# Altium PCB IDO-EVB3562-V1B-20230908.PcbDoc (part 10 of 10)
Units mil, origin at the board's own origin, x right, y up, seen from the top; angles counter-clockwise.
Board outline 5314.96 x 3543.31 mil, 4 copper layers (TOP, L2-VCC, L3-GND, BOTTOM), stack 28.8 mil thick; 747 components, 560 nets, 2514 pads, 1964 vias.
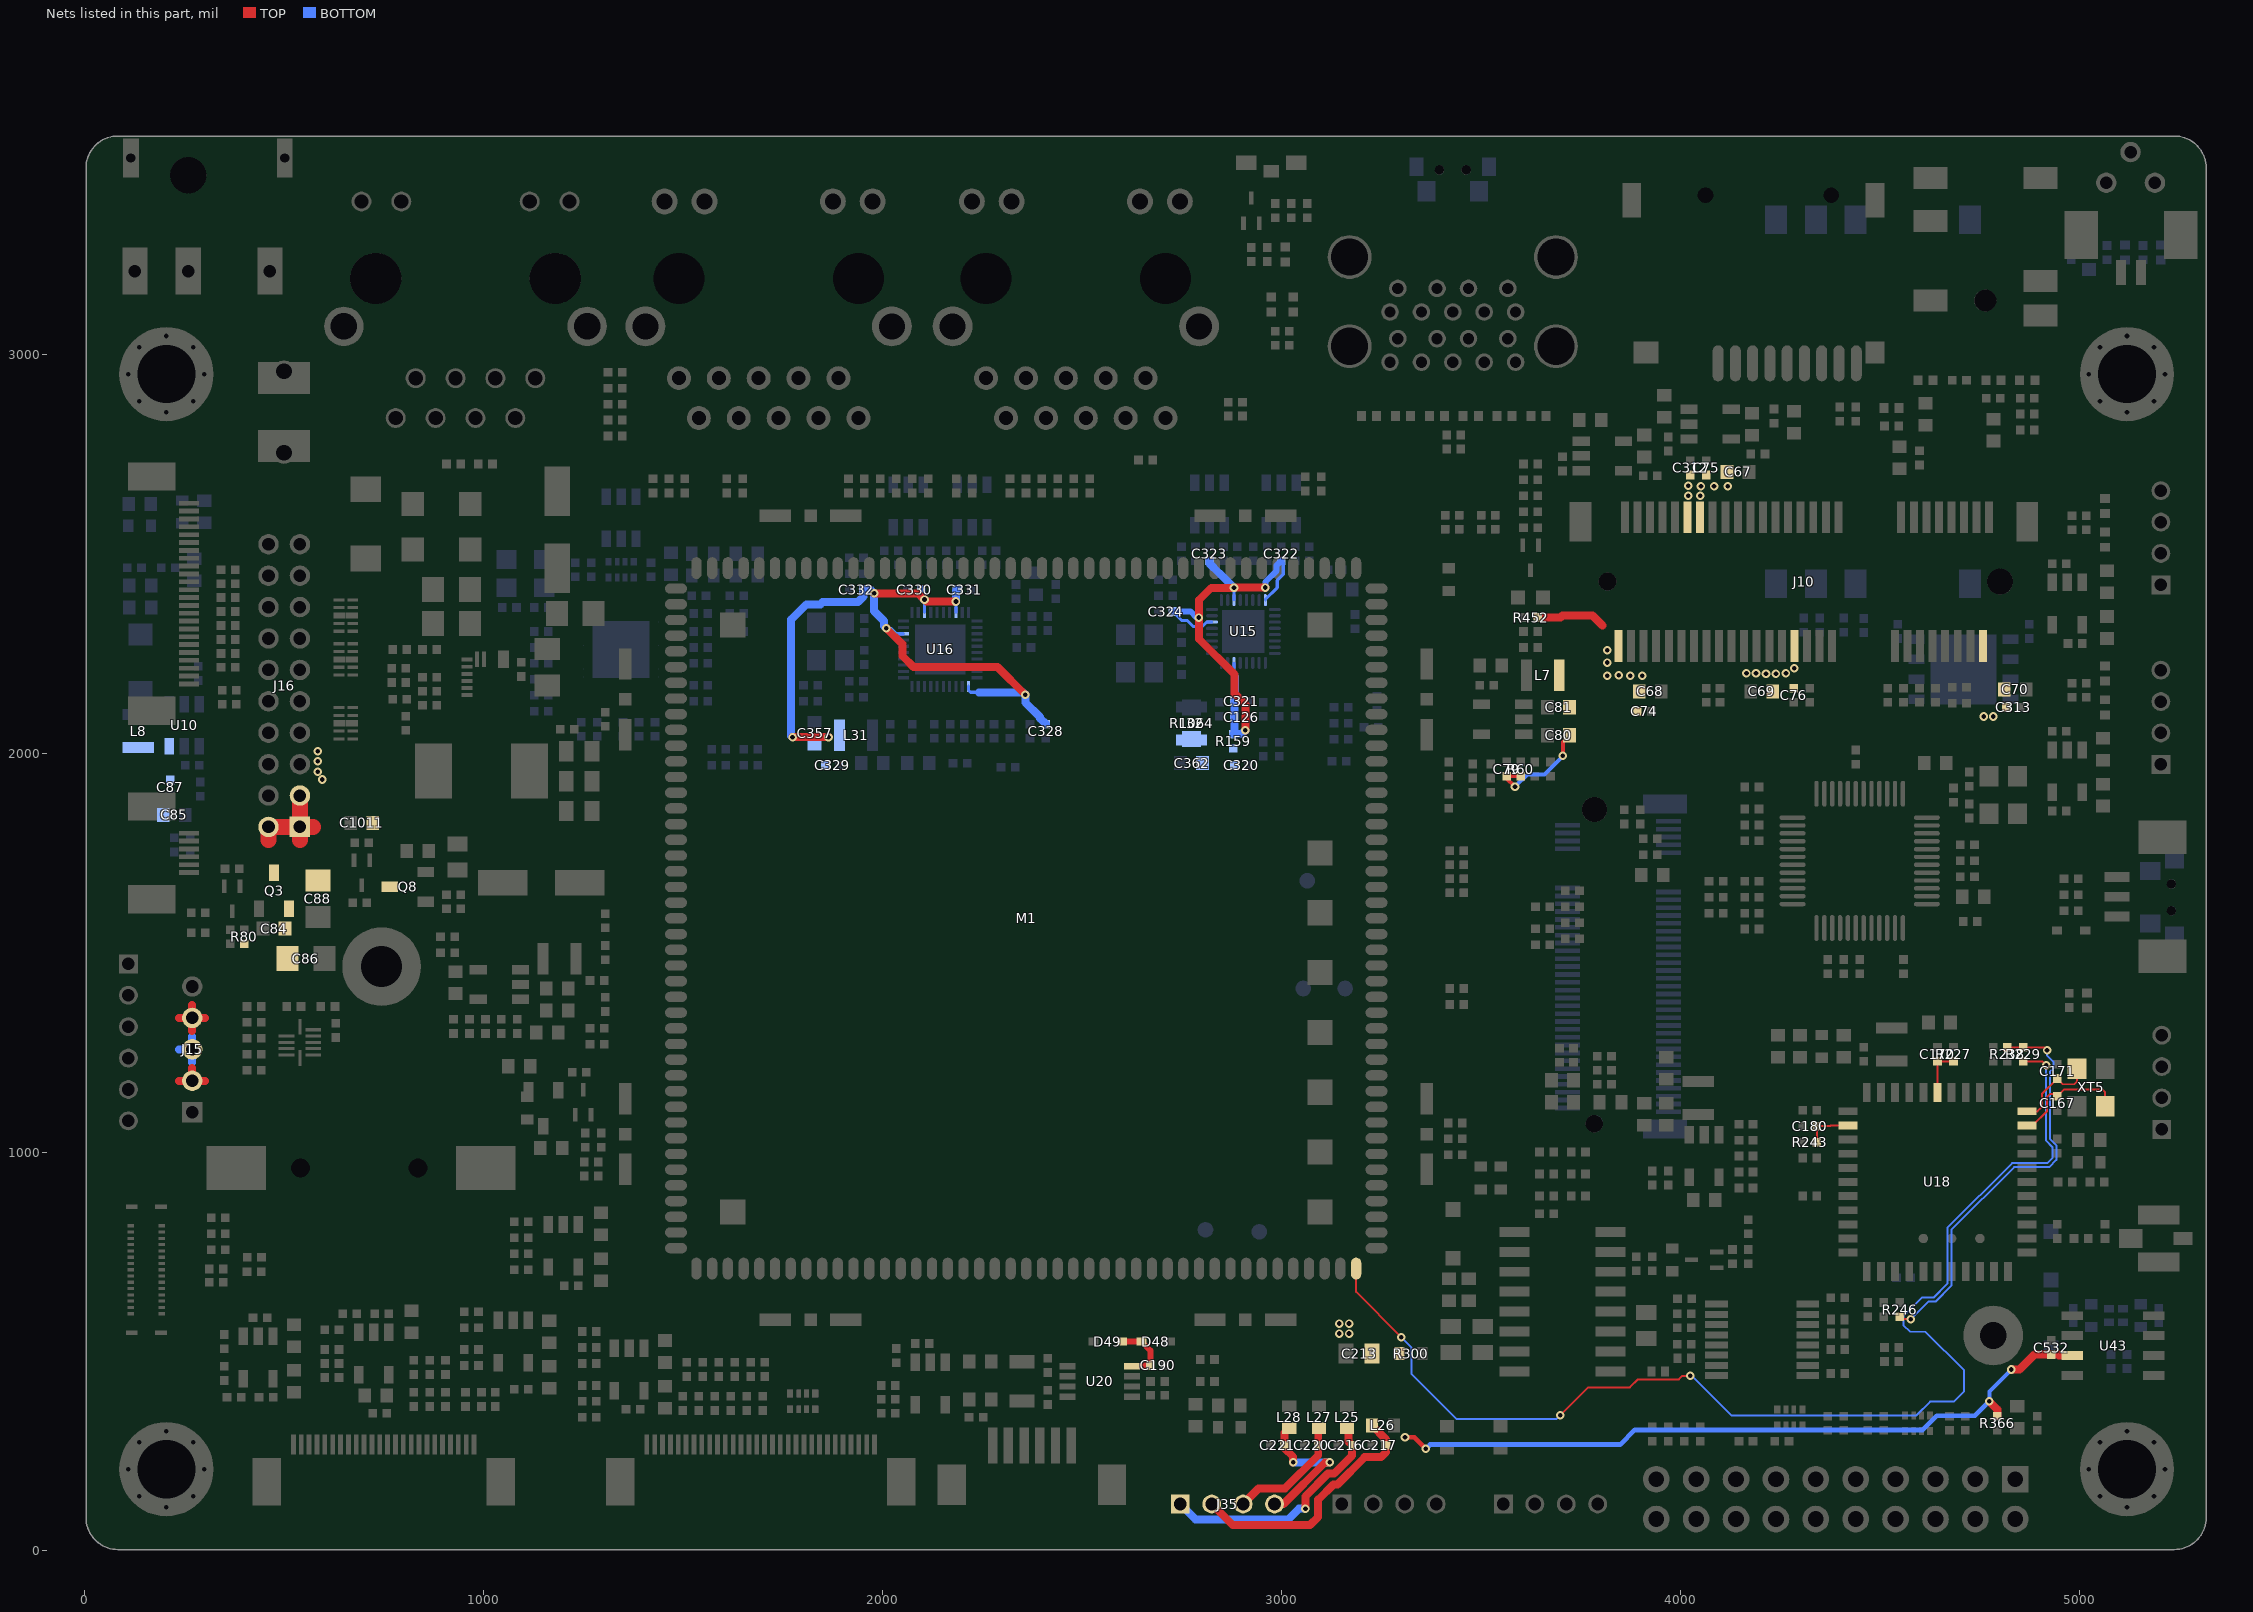
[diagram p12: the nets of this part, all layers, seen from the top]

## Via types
v1: diameter 21.65, hole 11.81, TOP to BOTTOM, 1964 vias

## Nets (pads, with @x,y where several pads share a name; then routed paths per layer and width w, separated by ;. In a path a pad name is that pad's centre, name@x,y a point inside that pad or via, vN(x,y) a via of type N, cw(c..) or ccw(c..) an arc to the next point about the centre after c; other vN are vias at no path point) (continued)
VDD10_PHY0: C328.2 C329.2 C330.2 C331.2 C332.2 C357.2 L31.2 U16.3 U16.8 U16.21 U16.38 | length 1806.9
  TOP w20: v1(1775,2040) v1(1865,2040) ; v1(1979.4,2400.51) 2090.12,2400.51 v1(2105.63,2385) 2110.63,2380 v1(2184.37,2380) ; v1(2010,2313.35) 2050,2273.35 2050,2244 2078,2216 2289,2216 v1(2358.47,2146.53)
  BOTTOM w8: v1(2010,2313.35) 2011.35,2312 2022.62,2312 2035.25,2299.37 U16.38@2052.48,2299.37 ; U16.3@2105.63,2352.52 v1(2105.63,2385) ; U16.8@2184.37,2352.52 v1(2184.37,2380) ; U16.21@2215.87,2167.48 2215.87,2158.13 2221.5,2152.5 2242.5,2152.5
  BOTTOM w20: v1(1775,2040) 1771.57,2043.43 1771.57,2334.79 1809.97,2373.18 1844.68,2373.18 1850.33,2378.84 1938.84,2378.84 1952.72,2392.72 C332.2@1952.72,2410 1969.91,2410 v1(1979.4,2400.51) 1979.4,2356.24 2004.43,2331.2 2004.43,2318.91 v1(2010,2313.35) ; C330.2@2097.72,2410 2097.72,2392.91 v1(2105.63,2385) ; v1(2184.37,2380) 2184.37,2407.09 C331.2@2187.28,2410 ; 2242.5,2152.5 2352.5,2152.5 v1(2358.47,2146.53) 2358.47,2127.17 2395.37,2090.27 2395.37,2087.35 C328.2@2410,2072.72
VDD10_PHY2: C320.2 C362.2 L32.2 R159.1 R1064.2
VDD10_RTL: C126.1 C321.2 C322.2 C323.2 C324.2 R159.2 U15.3 U15.8 U15.22 U15.30 | length 1287.9
  TOP w20: v1(2910,2057.32) 2910,2122 2882.43,2149.57 2882.43,2197.57 2793.33,2286.67 v1(2793.33,2339.87) 2793.33,2383.33 2824.57,2414.57 v1(2881.38,2414.57) 2881.82,2415 v1(2960.12,2415)
  BOTTOM w8: C324.2@2727.72,2355 2750.15,2332.57 2764.58,2332.57 2779.95,2317.2 2801.2,2317.2 2812.62,2328.62 U15.30@2826.26,2328.62 ; U15.22@2881.38,2226.26 2881.38,2193.62 2884.63,2190.37 ; U15.3@2881.38,2383.74 v1(2881.38,2414.57) ; U15.8@2960.12,2383.74 2960.12,2385.12 2990,2415 2990,2433.07 3005,2448.07 3005,2477.28 C322.2@3000,2482.28
  BOTTOM w15: C324.2@2727.72,2355 2772.87,2355 2788,2339.87 v1(2793.33,2339.87) ; v1(2960.12,2415) 2960.12,2429.12 2988.32,2457.33 2988.32,2470.6 C322.2@3000,2482.28
  BOTTOM w20: C323.2@2820,2482.28 2820,2475.78 2844.78,2451 2844.95,2451 v1(2881.38,2414.57) ; 2884.63,2190.37 2884.63,2132.35 C321.2@2882.28,2130 C126.1@2882.28,2090 2882.28,2050 R159.2@2880,2047.72 2900.4,2047.72 v1(2910,2057.32)
VDD_3V8: C67.2 C68.2 C69.2 C70.2 C74.2 C75.2 C76.2 C79.2 C80.2 C81.2 C312.2 C313.2 J10.2 J10.24 J10.39 J10.41 J10.52 L7.2 R60.2 R452.2 | length 455.3
  TOP w10: v1(3585.93,1915.93) 3565,1936.86 C79.2@3565,1942.28 R60.2@3600,1942.28 ; v1(3705.83,1993.37) 3705.83,2028.27 C80.2@3722.56,2045
  TOP w20: R452.2@3642.72,2340 3700,2340 3705,2345 3780,2345 3805,2320
  BOTTOM w10: v1(3585.93,1915.93) 3617,1947 3659.46,1947 v1(3705.83,1993.37)
  other v1: 4761,2092 4785,2092 3817,2194 3875,2194 3905,2194 3846,2195 4215,2199 4240,2199 4166,2200 4190,2200 4265,2200 4286,2213 3817,2227 3817,2258 4020,2645 4050,2645 4052,2669 4085,2669 4119,2669 4020,2670
VDD_5V: C85.2 C87.2 C213.2 C532.1 C1011.2 J15.3 L8.1 Q8.3 R300.2 R366.1 U10.6 U43.3 | length 1941.3
  TOP w12: v1(3310,285) 3333.65,285 v1(3362.43,256.22)
  TOP w20: v1(4775,375) 4795,355 R366.1@4795,337.72 ; v1(4830,455) 4850.83,455 4888.11,492.28 C532.1@4929.99,492.28 4947.72,492.28 4950,490 U43.3@4982.64,490
  BOTTOM w10: v1(4775,375) 4775,400 v1(4830,455)
  BOTTOM w12: v1(3362.43,256.22) 3373.03,266.83 3849.83,266.83 3886.46,303.46 4607.59,303.46 4643.12,339 4739,339 v1(4775,375)
  BOTTOM w20: 237.41,1257.48 J15.3@270,1257.48 ; 270,1224.89 J15.3@270,1257.48 ; 270,1290.07 J15.3@270,1257.48
  other v1: 3145,545 3170,545 3145,570 3170,570 596,1934 585,1953.35 585,1980 585,2005
VDD_LCD: C84.2 C86.2 J15.2 J15.4 Q3.2 R80.2 | length 228.2
  TOP w20: 237.41,1178.74 J15.2@270,1178.74 ; 237.41,1336.22 J15.4@270,1336.22 ; 270,1211.33 J15.2@270,1178.74 ; 270,1303.63 J15.4@270,1336.22 ; 270,1368.81 J15.4@270,1336.22 ; 302.59,1178.74 J15.2@270,1178.74 ; 302.59,1336.22 J15.4@270,1336.22
VDD_LCD_: C88.2 J16.1 J16.2 J16.3 Q3.3 | length 255.3
  TOP w40: 461.26,1782.41 J16.2@461.26,1815 J16.1@540,1815 ; 540,1782.41 J16.1@540,1815 ; J16.3@540,1893.74 J16.1@540,1815 ; 572.59,1815 J16.1@540,1815
VDD_RTC: C190.1 D48.C D49.C U20.8 | length 165.8
  TOP w15: D49.C@2600.43,525 D48.C@2649.57,525 2672.28,502.29 C190.1@2672.28,465.01 ; U20.8@2625.71,463.39 2653.39,463.39 2655,465 C190.1@2672.28,465.01
VOLN: C216.1 J35.1 L25.2 | length 605
  TOP w20: v1(3060.51,106) 3060.51,137.15 3117.36,194 3132.7,194 3177.72,239.02 C216.1@3177.72,265 3168.13,274.59 3168.13,304.31 L25.2@3165,307.44
  BOTTOM w20: J35.1@2746.89,117.72 2785.51,79.09 3017.74,79.09 3044.64,106 v1(3060.51,106)
VOLP: C217.1 J35.2 L26.2 | length 641.7
  TOP w20: J35.2@2825.63,117.72 2878.35,65 3072,65 3092.51,85.51 3092.51,128.51 3131,167 3141.05,167 3209.05,235 3250,235 3262.72,247.72 C217.1@3262.72,265 3262.72,279.72 L26.2@3227.44,315
VORN: C220.1 J35.3 L27.2 | length 307.3
  TOP w20: J35.3@2904.37,117.72 2942.99,156.34 3008.98,156.34 3092.72,240.08 C220.1@3092.72,265 3092.72,305.16 L27.2@3095,307.44
VORP: C221.1 J35.4 L28.2 | length 372.4
  TOP w20: J35.4@2983.11,117.72 3005.72,117.72 3110.17,222.17 v1(3121.34,222.17) ; L28.2@3020,307.44 3007.72,295.16 C221.1@3007.72,265 3007.72,258.46 3030,236.18 v1(3030,222.17)
  BOTTOM w20: v1(3030,222.17) v1(3121.34,222.17)
WIFI1T1R_CLK: C170.2 R227.2 U18.17 | length 117.9
  TOP w5: U18.17@4645,1149.41 C170.2@4645,1227.28 R227.2@4685,1227.28
WIFI1T1R_XTAL_IN: C167.2 U18.10 XT5.3 | length 297.4
  TOP w5: U18.10@4869.41,1066.73 4883.73,1066.73 4920,1103 4920,1138.72 4927.28,1146 4938.72,1146 C167.2@4945,1139.72 4962.28,1157 5058,1157 5065.43,1149.57 XT5.3@5065.43,1114.76
WIFI1T1R_XTAL_OUT: C171.2 U18.11 XT5.1 | length 219.4
  TOP w5: U18.11@4869.41,1102.17 4895.17,1102.17 4907,1114 4907,1146.28 C171.2@4945,1184.28 4959.28,1170 4988,1170 4994.57,1176.57 XT5.1@4994.57,1209.24
WIFI_REG_ON_H: R229.2 R238.1 R246.1 | length 1038.1
  TOP w5: R246.1@4550,587.28 4556.15,581.13 v1(4578.05,581.13) ; R238.1@4820,1262.72 R229.2@4860,1262.72 4912.44,1262.72 v1(4919.72,1255.44)
  BOTTOM w5: v1(4578.05,581.13) 4621.92,625 4640,625 4680,665 4680,805 4837.35,962.36 4924.79,962.36 4943.15,980.71 4943.15,1016.86 4926.67,1033.33 4926.67,1200.83 4936,1210.16 4936,1225.35 4919.72,1241.63 v1(4919.72,1255.44)
WIFI_REG_ON_H_GPIO0_A0_D: M1.172 R229.1 | length 3059.6
  TOP w5: M1.172@3187.6,707.87 3187.6,649.35 v1(3300.95,536) ; v1(3699.53,340) 3769.53,410 3873.89,410 3894.19,430.3 3996.95,430.3 4005.65,439 v1(4025,439) ; R229.1@4860,1227.28 4908.15,1227.28 v1(4917.67,1217.75)
  BOTTOM w5: v1(3300.95,536) 3326.33,510.62 3326.33,444.39 3440.39,330.33 3689.86,330.33 v1(3699.53,340) ; v1(4025,439) 4029.35,439 4128.24,340.1 4592.36,340.1 4626.76,374.5 4685.7,374.5 4711.74,400.54 4711.74,452.65 4614.83,549.57 4576.3,549.57 4559.72,566.14 4559.72,588.72 4606,635 4635,635 4670,670 4670,810 4832.36,972.36 4920.65,972.36 4933.15,984.85 4933.15,1012.71 4916.67,1029.18 4916.67,1216.75 v1(4917.67,1217.75)
WIFIBT_32KIN_1T1R: C180.2 R243.2 U18.24 | length 118.6
  TOP w5: R243.2@4342.72,1025 C180.2@4342.72,1065 4376,1065 4377.73,1066.73 U18.24@4420.59,1066.73
pads on no net: D33.5 D34.5 D35.5 D36.5 D80.5 HOLE5. HOLE9. HOLE10. HOLE11. J1.1 J6. J10.1 J10.3 J10.5 J10.6 J10.7 J10.11 J10.13 J10.16 J10.17 J10.19 J10.20 J10.23 J10.25 J10.28 J10.30 J10.31 J10.32 J10.33 J10.44 J10.45 J10.46 J10.47 J10.48 J10.49 J10.51 J10.53 J10.54 J11.C6 J11.CD1 J11.CD2 J16.4 J16.19 J16.20 J18.26 J18.30 J19.20 J19.21 J19.23 J19.24 J20.10 J20.18 J20.28 J21. J22. J23.7 J23.15 J23.16 J27.5 J27.6 J27.7 J27.8 J27.10 J27.11 J27.13 J27.17 J27.19 J27.20 J27.22 J27.23 J27.24 J27.25 J27.26 J27.28 J27.29 J27.30 J27.31 J27.32 J27.34 J27.35 J27.36 J27.37 J27.38 J27.40 J27.42 J27.44 J27.46 J27.48 J27.56 J27.58 J27.67 J27.69 J27.77 J27.78 J37. J37.6 J42.14 J42.15 J42.17 J42.18 J45.2 J47. LED1.3 SW5. SW6. U7.2 U7.4 U7.8 U7.38 U7.43 U7.44 U7.45 U7.46 U7.47 U8.2 U8.4 U8.5 U15.27 U16.31 U17.13 U17.18 U17.27 U18.4 U18.5 U18.7 U18.8 U18.25 U18.26 U18.27 U18.28 U18.30 U18.32 U18.35 U18.37 U18.38 U18.39 U18.40 U18.45 U18.46 U18.47 U20.3 U20.7 U70.11

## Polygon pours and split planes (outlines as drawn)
VDD_3V8 on TOP "TOP-VDD_3V8" (solid, pour order 56): 21 vertices, not listed, extent 4005,2541 4148,2734
VCC5V_SYS on TOP "TOP-VCC5V_SYS" (solid, pour order 23): 3877,2762 3833,2762 3829,2766 3829,2824 3849,2844 3915,2844 3928.5,2830.5 3928.5,2778.5 3920,2770 3886.86,2770 3885,2770 3877,2762
no net on TOP "TOP-No Net" (solid, pour order 32): 25 vertices, not listed, extent 4845,956 5023.5,1053
GND on TOP "TOP-GND" (solid, pour order 122): 90 vertices, not listed, extent 23.7,23.7 5298.66,3527.01
VDD_LCD on TOP "TOP-VDD_LCD" (solid, pour order 95): 28 vertices, not listed, extent 206,1155 541,1633
N70210968 on TOP "TOP-N70210968" (solid, pour order 9): 4083,1078 4044,1078 4036,1070 4036,1020 4034,1018 4006,1018 4001,1023 4001,1103 4006,1108 4084,1108 4086,1106 4086,1081 4083,1078
VCC2V8_DVP on TOP "TOP-VCC2V8_DVP" (solid, pour order 28): 487,456 463,456 460,453 460,340 469,331 532,331 539,338 539,412 535,416 502,416 492,426 492,451 487,456
VCC_SIM on TOP "TOP-VCC_SIM" (solid, pour order 54): 4305,2345 4305,2377 4315,2387 4522,2387 4547,2362 4615,2362 4627,2350 4627,2319 4625,2317 4527,2317 4506,2338 4312,2338 4305,2345
VDD_3V8 on TOP "TOP-VDD_3V8 1" (solid, pour order 43): 26 vertices, not listed, extent 4155,2131 4299,2314
VDD_3V8 on TOP "TOP-VDD_3V8 2" (solid, pour order 90): 24 vertices, not listed, extent 3682,2025 3919,2339
N69841804 on TOP "TOP-N69841804" (solid, pour order 99): 17 vertices, not listed, extent 420,2470 880.5,2790
no net on TOP "TOP-No Net 1" (solid, pour order 35): 21 vertices, not listed, extent 4987,2223 5089,2351
VCC5V0_HUB3 on TOP "TOP-VCC5V0_HUB3" (solid, pour order 62): 25 vertices, not listed, extent 4993,2374 5225.62,2497
VCC_DMIC on TOP "TOP-VCC_DMIC" (solid, pour order 66): 2558,285 2554,281 2490,217 2465,217 2461,221 2461,316 2475,330 2855,330 2860,325 2860,300 2845,285 2815,285 2558,285
VCC3V3_SD_OUT on TOP "TOP-VCC3V3_SD_OUT" (solid, pour order 12): 3605,1255 3600.56,1255 3520,1335.56 3520,1345 3535,1360 3555,1360 3625,1290 3625,1275 3605,1255
VCC_OUT on TOP "TOP-VCC_OUT" (solid, pour order 89): 27 vertices, not listed, extent 3125.5,79 3584,280
VCC2V8_DVP2 on TOP "TOP-VCC2V8_DVP2" (solid, pour order 34): 26 vertices, not listed, extent 1381,241 1474,424
VCC_M2 on TOP "TOP-VCC_M2" (solid, pour order 53): 45 vertices, not listed, extent 3710,1102 3813,1269
no net on TOP "TOP-No Net 2" (solid, pour order 68): 35 vertices, not listed, extent 4778,120 4920,326
N69774914 on TOP "TOP-N69774914" (solid, pour order 14): 34 vertices, not listed, extent 4489,1125 4573,1245
VCC_3V3 on TOP "TOP-VCC_3V3" (solid, pour order 26): 23 vertices, not listed, extent 235,2524 360,2622
VCC5V_SYS on TOP "TOP-VCC5V_SYS 1" (solid, pour order 97): 39 vertices, not listed, extent 4785,1365 5079,1930
VDD_3V8 on TOP "TOP-VDD_3V8 3" (solid, pour order 60): 17 vertices, not listed, extent 4744,2077.86 4832,2310
VCC_1V8_OUT on TOP "TOP-VCC_1V8_OUT" (solid, pour order 3): 1433,1831 1433,1824 1408.5,1799.5 1374.5,1799.5 1369,1805 1369,1829 1370,1830 1370,1846 1384,1860 1419,1860 1433,1846 1433,1831
no net on TOP "TOP-No Net 3" (solid, pour order 44): 19 vertices, not listed, extent 4335,1125 4479,1255
VCC5V_SYS on TOP "TOP-VCC5V_SYS 2" (solid, pour order 105): 201 vertices, not listed, extent 2945,1195 3205,1705
no net on TOP "TOP-No Net 4" (solid, pour order 58): 64 vertices, not listed, extent 4203,2735.5 4365,3029
VCC_1V8_OUT on TOP "TOP-VCC_1V8_OUT 1" (solid, pour order 74): 20 vertices, not listed, extent 1775,1458 2485,1661
VCC3V3_SPK on TOP "TOP-VCC3V3_SPK" (solid, pour order 70): 26 vertices, not listed, extent 3550.5,677 4003,856
VCC_TP on TOP "TOP-VCC_TP" (solid, pour order 31): 50 vertices, not listed, extent 430,1302.69 527,1402.83
VCC_M2 on TOP "TOP-VCC_M2 1" (solid, pour order 84): 142 vertices, not listed, extent 3759,1481.33 3920,1835
VCC_1V8_OUT on TOP "TOP-VCC_1V8_OUT 2" (solid, pour order 1): 1387,1631 1393,1625 1393,1601 1381,1589 1343,1589 1332,1600 1332,1621 1342,1631 1387,1631
VCC_3V3 on TOP "TOP-VCC_3V3 1" (solid, pour order 30): 21 vertices, not listed, extent 459.5,514 572,665.25
VCC3V3_SYS on TOP "TOP-VCC3V3_SYS" (solid, pour order 78): 38 vertices, not listed, extent 1090,1125 1280,1555
VCC3V3_SYS on TOP "TOP-VCC3V3_SYS 1" (solid, pour order 107): 21 vertices, not listed, extent 1695.33,980 2505,1446
N69227900 on TOP "TOP-N69227900" (solid, pour order 29): 1125,1530 1161,1530 1165,1526 1165,1445 1114,1445 1072,1445 1070,1447 1070,1475 1070,1523 1077,1530 1125,1530
VCC_3V3 on TOP "TOP-VCC_3V3 2" (solid, pour order 11): 1390,550 1390,485 1392,483 1412,483 1417,488 1417,494 1434,511 1440,511 1475,511 1479,515 1479,551 1473,557 1397,557 1390,550
VCC_3V3 on TOP "TOP-VCC_3V3 3" (solid, pour order 57): 22 vertices, not listed, extent 2840,155 2935,440
VCC5V_SYS on TOP "TOP-VCC5V_SYS 3" (solid, pour order 40): 3451.5,971.5 3443,980 3443,1009 3448,1014 3473,1014 3475,1016 3475,1031 3483,1039 3505,1039 3561,1039 3570,1030 3570,980 3570,950 3473,950 3451.5,971.5
VCC_LEDK- on TOP "TOP-VCC_LEDK-" (solid, pour order 5): 18 vertices, not listed, extent 177,2546 290,2593
VCC_3V3 on TOP "TOP-VCC_3V3 4" (solid, pour order 8): 4160,280 4160,257.13 4152.87,250 4084,250 4079,255 4079,280 4083,284 4095,284 4128,317 4157,317 4160,314 4160,280
VCC5V_SYS on TOP "TOP-VCC5V_SYS 4" (solid, pour order 38): 4107,2825 4096,2836 4096,2902 4109,2915 4186,2915 4204,2897 4204,2852.86 4204,2831 4198,2825 4107,2825
VDD_5V on TOP "TOP-VDD_5V" (solid, pour order 50): 21 vertices, not listed, extent 3130,467.5 3315,590
VCC3V3_SD_OUT on TOP "TOP-VCC3V3_SD_OUT 1" (solid, pour order 0): 3985,2183 3976,2192 3976,2216 3980.5,2220.5 4030.5,2220.5 4038,2213 4038,2196.57 4031.15,2189.72 4031.15,2187.15 4027,2183 3985,2183
VCC_1V8_OUT on TOP "TOP-VCC_1V8_OUT 3" (solid, pour order 2): 293.9,2482.9 238.1,2482.9 236,2485 236,2511 238.95,2513.95 295.01,2513.95 295.01,2514 340,2514 350,2504 350,2496 342.5,2488.5 299.5,2488.5 293.9,2482.9
VCC3V3_SYS on TOP "TOP-VCC3V3_SYS 2" (solid, pour order 93): 19 vertices, not listed, extent 3610,1276 4377,1439.56
VCC_3V3 on TOP "TOP-VCC_3V3 5" (solid, pour order 16): 1135,552 1104,552 1100,556 1100,609 1107,616 1190,616 1196,610 1196,567 1181,552 1135,552
VCC2V8_DVP1 on TOP "TOP-VCC2V8_DVP1" (solid, pour order 63): 44 vertices, not listed, extent 951.01,238 1184,496
N70208813 on TOP "TOP-N70208813" (solid, pour order 88): 24 vertices, not listed, extent 3210,665 3572,925
VCC5V0_HUB2 on TOP "TOP-VCC5V0_HUB2" (solid, pour order 96): 68 vertices, not listed, extent 3546,2850 4075,3180
HUB_3V3 on TOP "TOP-HUB_3V3" (solid, pour order 15): 49 vertices, not listed, extent 4350,1470 4427,1598
VCC5V_SYS on TOP "TOP-VCC5V_SYS 5" (solid, pour order 52): 4034,838 3908,838 3897,849 3897,912 3913,928 3994,928 4003,937 4003,944.86 4010,951.86 4010,958 4011,959 4040,959 4049,950 4049,853 4034,838
VDD_5V on TOP "TOP-VDD_5V 1" (solid, pour order 72): 60 vertices, not listed, extent 565,1650 796,2023
HUB_3V3 on TOP "TOP-HUB_3V3 1" (solid, pour order 18): 20 vertices, not listed, extent 4552,1863 4640,1997.07
VCC1V8_DVP on TOP "TOP-VCC1V8_DVP" (solid, pour order 33): 20 vertices, not listed, extent 1225,625 1323,737
no net on TOP "TOP-No Net 5" (solid, pour order 59): 23 vertices, not listed, extent 3830,1095 4091,1201
no net on TOP "TOP-No Net 6" (solid, pour order 77): 58 vertices, not listed, extent 825,1880 1056,2210
VCC3V3_SYS on TOP "TOP-VCC3V3_SYS 3" (solid, pour order 13): 18 vertices, not listed, extent 553,1302 677,1379
GND_EARTH on TOP "TOP-GND_EARTH" (solid, pour order 111): 61 vertices, not listed, extent 585,3020 2855,3527.01
VCC_3V3 on TOP "TOP-VCC_3V3 6" (solid, pour order 19): 2146.14,452 2145,453.14 2145,505 2145,519 2153,527 2228,527 2236,519 2236,457 2231,452 2146.14,452
VCC_3V3 on TOP "TOP-VCC_3V3 7" (solid, pour order 76): 43 vertices, not listed, extent 1035,795 1325,1100
PA_5V on TOP "TOP-PA_5V" (solid, pour order 80): 34 vertices, not listed, extent 3335,470 3946,628
USB_OTG on TOP "TOP-USB_OTG" (solid, pour order 61): 3825,3045 3825,2945 3775,2895 3775,2770 3725,2770 3725,2930 3725,2965 3750,2990 3750,3055 3755,3060 3760,3065 3815,3065 3825,3055 3825,3045
N69764515 on TOP "TOP-N69764515" (solid, pour order 17): 3590,2105 3585,2110 3585,2235 3595,2245 3625,2245 3632,2238 3632,2235 3631.5,2235 3631.5,2155 3632,2155 3632,2111 3626,2105 3590,2105
N69774891 on TOP "TOP-N69774891" (solid, pour order 45): 4489,1295 4481,1303 4481,1360 4491,1370 4625,1370 4640,1355 4640,1300 4635,1295 4489,1295
VCC_3V3 on TOP "TOP-VCC_3V3 8" (solid, pour order 20): 21 vertices, not listed, extent 750,526 839,644
VCC_DCIN on TOP "TOP-VCC_DCIN" (solid, pour order 65): 403,3014 403,2920 568,2920 568,3007 496.5,3078.5 467.5,3078.5 413,3024 403,3014
VCC_SYS on TOP "TOP-VCC_SYS" (solid, pour order 103): 41 vertices, not listed, extent 935,2212 1218,2667
no net on TOP "TOP-No Net 7" (solid, pour order 104): 53 vertices, not listed, extent 830,1435 1229,2075
VCC_LEDA+ on TOP "TOP-VCC_LEDA+" (solid, pour order 71): 24 vertices, not listed, extent 105,2313 290,2650
VCC5V0_HUB4 on TOP "TOP-VCC5V0_HUB4" (solid, pour order 64): 24 vertices, not listed, extent 4993,1920.5 5225.62,2075
N69774891 on TOP "TOP-N69774891 1" (solid, pour order 21): 4335,1090 4330,1095 4330,1120 4330,1140 4350,1160 4424.85,1160 4435,1149.86 4435,1125 4445,1115 4445,1095 4440,1090 4335,1090
VDD_LCD_ on TOP "TOP-VDD_LCD_" (solid, pour order 85): 17 vertices, not listed, extent 425,1650 625,1923
VCC5V_SYS on TOP "TOP-VCC5V_SYS 6" (solid, pour order 47): 18 vertices, not listed, extent 3430,2103 3525,2250
VCC3V3_SYS on BOTTOM "BOTTOM-VCC3V3_SYS" (solid, pour order 75): 53 vertices, not listed, extent 4225,1295 4780,1415
VCC_1V8_OUT on BOTTOM "BOTTOM-VCC_1V8_OUT" (solid, pour order 91): 23 vertices, not listed, extent 2420,1455 3435,1602
VCC3V3_SYS on BOTTOM "BOTTOM-VCC3V3_SYS 1" (solid, pour order 94): 103 vertices, not listed, extent 1220,1220 1786,1567.5
VCC_M2 on BOTTOM "BOTTOM-VCC_M2" (solid, pour order 92): 103 vertices, not listed, extent 3675,1095 3890,1530
VCC_RMII on BOTTOM "BOTTOM-VCC_RMII" (solid, pour order 49): 22 vertices, not listed, extent 1546,2383 1651,2550
USB_OTG on BOTTOM "BOTTOM-USB_OTG" (solid, pour order 69): 3740,3195 3550,3195 3540,3185 3540,3150 3550,3140 3610,3140 3655,3095 3710,3095 3750,3055 3750,3025 3760,3015 3770,3015 3815,3060 3815,3120 3740,3195
VCC5V_SYS on BOTTOM "BOTTOM-VCC5V_SYS" (solid, pour order 116): 140 vertices, not listed, extent 3825,1830 5120,3015
GND on BOTTOM "BOTTOM-GND" (solid, pour order 6): 20 vertices, not listed, extent 2982,2505 3028,2649.48
VCC1V8_DVP on BOTTOM "BOTTOM-VCC1V8_DVP" (solid, pour order 81): 33 vertices, not listed, extent 235,286 910,830
VCC3V3_SD_OUT on BOTTOM "BOTTOM-VCC3V3_SD_OUT" (solid, pour order 83): 33 vertices, not listed, extent 4013,1240 4148,1962
VCC_1V8_OUT on BOTTOM "BOTTOM-VCC_1V8_OUT 1" (solid, pour order 7): 1815,1668 1852,1631 1852,1613 1829,1590 1813,1590 1775,1628 1775,1651 1792,1668 1815,1668
VCCA_RMII on BOTTOM "BOTTOM-VCCA_RMII" (solid, pour order 41): 32 vertices, not listed, extent 1386,2340 1542,2463
no net on BOTTOM "BOTTOM-No Net" (solid, pour order 27): 40 vertices, not listed, extent 1811.57,1955 1910,2086
N69811283 on BOTTOM "BOTTOM-N69811283" (solid, pour order 51): 21 vertices, not listed, extent 90,2080 225,2185
VCC_SIM on BOTTOM "BOTTOM-VCC_SIM" (solid, pour order 22): 4540,2266 4523,2283 4523,2326 4526,2329 4564,2329 4565,2330 4576,2341 4620,2341 4633,2328 4633,2272 4627,2266 4540,2266
VCC5V_SYS on BOTTOM "BOTTOM-VCC5V_SYS 1" (solid, pour order 98): 118 vertices, not listed, extent 3105,1639.5 3503.25,2250
VCC_LEDA+ on BOTTOM "BOTTOM-VCC_LEDA+" (solid, pour order 55): 167.5,2245 115,2245 105,2255 105,2335 109.3,2339.3 136.19,2339.3 136.19,2340 145,2340 150,2345 150,2435 155,2440 185,2440 223.5,2401.5 223.5,2301 167.5,2245
no net on BOTTOM "BOTTOM-No Net 1" (solid, pour order 119): 476 vertices, not listed, extent 38,53.7 3329,2040
VCC1V2_DVP on BOTTOM "BOTTOM-VCC1V2_DVP" (solid, pour order 79): 43 vertices, not listed, extent 282,327 804,790
VCC_3V3 on BOTTOM "BOTTOM-VCC_3V3" (solid, pour order 118): 852 vertices, not listed, extent 245,290 2941,1540
VCC3V3_PHY2 on BOTTOM "BOTTOM-VCC3V3_PHY2" (solid, pour order 37): 31 vertices, not listed, extent 3018,2320 3138,2475
no net on BOTTOM "BOTTOM-No Net 2" (solid, pour order 117): 435 vertices, not listed, extent 910,726 5009,1531.28
VCC3V3_SD_OUT on BOTTOM "BOTTOM-VCC3V3_SD_OUT 1" (solid, pour order 42): 3476.79,1250 3445,1281.79 3445,1305 3490,1350 3565,1350 3590,1325 3590,1305 3555,1270 3515,1270 3495,1250 3476.79,1250
PHY0_REG_OUT on BOTTOM "BOTTOM-PHY0_REG_OUT" (solid, pour order 25): 56 vertices, not listed, extent 1960,2004 2077.95,2177
N69774891 on BOTTOM "BOTTOM-N69774891" (solid, pour order 67): 42 vertices, not listed, extent 4340,1110 4600,1355
VCC_M2 on BOTTOM "BOTTOM-VCC_M2 1" (solid, pour order 24): 74 vertices, not listed, extent 3688.52,1760 3834,1830
VCC3V3_SD_OUT on BOTTOM "BOTTOM-VCC3V3_SD_OUT 2" (solid, pour order 73): 18 vertices, not listed, extent 3976,2190 4355,2765
VCC3V3_SYS on BOTTOM "BOTTOM-VCC3V3_SYS 2" (solid, pour order 82): 72 vertices, not listed, extent 649,1190 1165,1355
VDD10_PHY2 on BOTTOM "BOTTOM-VDD10_PHY2" (solid, pour order 46): 23 vertices, not listed, extent 2732,1955.3 2895,2050
HUB_3V3 on BOTTOM "BOTTOM-HUB_3V3" (solid, pour order 101): 53 vertices, not listed, extent 4138.93,1500 4782,2004
GND_EARTH on BOTTOM "BOTTOM-GND_EARTH" (solid, pour order 115): 64 vertices, not listed, extent 72.5,2815.25 2855,3527.01
HUB_1V8 on BOTTOM "BOTTOM-HUB_1V8" (solid, pour order 87): 26 vertices, not listed, extent 4196,1590 4707,1945
VCC3V3_SYS on BOTTOM "BOTTOM-VCC3V3_SYS 3" (solid, pour order 106): 115 vertices, not listed, extent 2422,1340 3675,1537
VCC_OUT on BOTTOM "BOTTOM-VCC_OUT" (solid, pour order 102): 383 vertices, not listed, extent 3431,54 4915,270
VCC_LEDK- on BOTTOM "BOTTOM-VCC_LEDK-" (solid, pour order 10): 154,2554 154,2588 158,2592 259,2592 262,2589 262,2557 253,2548 160,2548 154,2554
GND on BOTTOM "BOTTOM-GND 1" (solid, pour order 121): 133 vertices, not listed, extent 23.7,23.7 5298.66,3527
VDD_3V8 on BOTTOM "BOTTOM-VDD_3V8" (solid, pour order 110): 222 vertices, not listed, extent 3805,1930 4848,2684
VCC_LEDA+ on BOTTOM "BOTTOM-VCC_LEDA+ 1" (solid, pour order 4): 22 vertices, not listed, extent 149,2602 221,2652
VCC_1V8_OUT on BOTTOM "BOTTOM-VCC_1V8_OUT 2" (solid, pour order 86): 109 vertices, not listed, extent 215,2390 620,2565
PHY2_REG_OUT on BOTTOM "BOTTOM-PHY2_REG_OUT" (solid, pour order 36): 75 vertices, not listed, extent 2733,2100 2853.74,2241
VCC_3V3 on BOTTOM "BOTTOM-VCC_3V3 1" (solid, pour order 100): 28 vertices, not listed, extent 273,2525 1195,2764
VCC_SIM on BOTTOM "BOTTOM-VCC_SIM 1" (solid, pour order 48): 29 vertices, not listed, extent 4204,2326 4367,2467
VCC3V3_PHY0 on BOTTOM "BOTTOM-VCC3V3_PHY0" (solid, pour order 39): 87 vertices, not listed, extent 2227.81,2327.05 2448,2414
VCC_3V3 on L2-VCC "L2-VCC-VCC_3V3" (solid, pour order 109): 35 vertices, not listed, extent 1076,2555 3079,2839
GND_EARTH on L2-VCC "L2-VCC-GND_EARTH" (solid, pour order 113): 49 vertices, not listed, extent 586,3019 2856,3526.01
VCC_DCIN on L2-VCC "L2-VCC-VCC_DCIN" (solid, pour order 114): 46 vertices, not listed, extent 52,1047 567,3351
VCC_3V3 on L2-VCC "L2-VCC-VCC_3V3 1" (solid, pour order 108): 29 vertices, not listed, extent 140,1390 375,2622.5
GND on L2-VCC "L2-VCC-GND" (solid, pour order 123): 90 vertices, not listed, extent 23.7,23.7 5298.66,3527.01
GND_EARTH on L3-GND "L3-GND-GND_EARTH" (solid, pour order 112): 46 vertices, not listed, extent 585,3020 2855,3527
GND on L3-GND "L3-GND-GND" (solid, pour order 120): 133 vertices, not listed, extent 23.7,23.7 5298.66,3527

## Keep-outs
TOP:
  region: 5277.49,2950 5275.55,2974.64 5269.78,2998.67 5260.32,3021.5 5247.41,3042.57 5231.36,3061.36 5212.57,3077.41 5191.5,3090.32 5168.67,3099.78 5144.64,3105.55 5120,3107.49 5095.36,3105.55 5071.33,3099.78 5048.5,3090.32 5041.47,3086.02 5027.43,3077.41 5008.64,3061.36 4992.59,3042.57 4979.68,3021.5 4970.22,2998.67 4964.45,2974.64 4962.51,2950 4964.45,2925.36 4970.22,2901.33 4979.68,2878.5 4992.59,2857.43 5008.64,2838.64 5027.43,2822.59 5041.47,2813.98 5048.5,2809.68 5071.33,2800.22 5095.36,2794.45 5120,2792.51 5144.64,2794.45 5168.67,2800.22 5191.5,2809.68 5212.57,2822.59 5231.36,2838.64 5247.41,2857.43 5260.32,2878.5 5269.78,2901.33 5275.55,2925.36 5277.49,2950
  region: 367.49,205 365.55,229.64 359.78,253.67 350.32,276.5 337.41,297.57 321.36,316.36 302.57,332.41 281.5,345.32 258.67,354.78 234.64,360.55 210,362.49 185.36,360.55 161.33,354.78 138.5,345.32 131.47,341.02 117.43,332.41 98.64,316.36 82.59,297.57 69.68,276.5 60.22,253.67 54.45,229.64 52.51,205 54.45,180.36 60.22,156.33 69.68,133.5 82.59,112.43 98.64,93.64 117.43,77.59 131.47,68.98 138.5,64.68 161.33,55.22 185.36,49.45 210,47.51 234.64,49.45 258.67,55.22 281.5,64.68 302.57,77.59 321.36,93.64 337.41,112.43 350.32,133.5 359.78,156.33 365.55,180.36 367.49,205
  region: 205,2800 191.93,2800.57 178.95,2802.28 166.18,2805.11 153.7,2809.05 141.61,2814.05 130,2820.1 118.96,2827.13 108.58,2835.09 98.93,2843.93 90.09,2853.58 82.13,2863.96 75.1,2875 69.05,2886.61 64.05,2898.7 60.11,2911.18 57.28,2923.95 55.57,2936.93 55,2950 55.57,2963.07 57.28,2976.05 60.11,2988.82 64.05,3001.3 69.05,3013.39 75.1,3025 82.13,3036.04 90.09,3046.42 98.93,3056.07 108.58,3064.91 118.96,3072.87 130,3079.9 141.61,3085.95 153.7,3090.95 166.18,3094.89 178.95,3097.72 191.93,3099.43 205,3100 218.07,3099.43 231.05,3097.72 243.82,3094.89 256.3,3090.95 268.39,3085.95 280,3079.9 291.04,3072.87 301.42,3064.91 311.07,3056.07 319.91,3046.42 327.87,3036.04 334.9,3025 340.95,3013.39 345.95,3001.3 349.89,2988.82 352.72,2976.05 354.43,2963.07 355,2950 354.43,2936.93 352.72,2923.95 349.89,2911.18 345.95,2898.7 340.95,2886.61 334.9,2875 327.87,2863.96 319.91,2853.58 311.07,2843.93 301.42,2835.09 291.04,2827.13 280,2820.1 268.39,2814.05 256.3,2809.05 243.82,2805.11 231.05,2802.28 218.07,2800.57 205,2800
  region: 5277.49,205 5275.55,229.64 5269.78,253.67 5260.32,276.5 5247.41,297.57 5231.36,316.36 5212.57,332.41 5191.5,345.32 5168.67,354.78 5144.64,360.55 5120,362.49 5095.36,360.55 5071.33,354.78 5048.5,345.32 5041.47,341.02 5027.43,332.41 5008.64,316.36 4992.59,297.57 4979.68,276.5 4970.22,253.67 4964.45,229.64 4962.51,205 4964.45,180.36 4970.22,156.33 4979.68,133.5 4992.59,112.43 5008.64,93.64 5027.43,77.59 5041.47,68.98 5048.5,64.68 5071.33,55.22 5095.36,49.45 5120,47.51 5144.64,49.45 5168.67,55.22 5191.5,64.68 5212.57,77.59 5231.36,93.64 5247.41,112.43 5260.32,133.5 5269.78,156.33 5275.55,180.36 5277.49,205
L2-VCC:
  region: 205,2800 191.93,2800.57 178.95,2802.28 166.18,2805.11 153.7,2809.05 141.61,2814.05 130,2820.1 118.96,2827.13 108.58,2835.09 98.93,2843.93 90.09,2853.58 82.13,2863.96 75.1,2875 69.05,2886.61 64.05,2898.7 60.11,2911.18 57.28,2923.95 55.57,2936.93 55,2950 55.57,2963.07 57.28,2976.05 60.11,2988.82 64.05,3001.3 69.05,3013.39 75.1,3025 82.13,3036.04 90.09,3046.42 98.93,3056.07 108.58,3064.91 118.96,3072.87 130,3079.9 141.61,3085.95 153.7,3090.95 166.18,3094.89 178.95,3097.72 191.93,3099.43 205,3100 218.07,3099.43 231.05,3097.72 243.82,3094.89 256.3,3090.95 268.39,3085.95 280,3079.9 291.04,3072.87 301.42,3064.91 311.07,3056.07 319.91,3046.42 327.87,3036.04 334.9,3025 340.95,3013.39 345.95,3001.3 349.89,2988.82 352.72,2976.05 354.43,2963.07 355,2950 354.43,2936.93 352.72,2923.95 349.89,2911.18 345.95,2898.7 340.95,2886.61 334.9,2875 327.87,2863.96 319.91,2853.58 311.07,2843.93 301.42,2835.09 291.04,2827.13 280,2820.1 268.39,2814.05 256.3,2809.05 243.82,2805.11 231.05,2802.28 218.07,2800.57 205,2800
L3-GND:
  region: 205,2800 191.93,2800.57 178.95,2802.28 166.18,2805.11 153.7,2809.05 141.61,2814.05 130,2820.1 118.96,2827.13 108.58,2835.09 98.93,2843.93 90.09,2853.58 82.13,2863.96 75.1,2875 69.05,2886.61 64.05,2898.7 60.11,2911.18 57.28,2923.95 55.57,2936.93 55,2950 55.57,2963.07 57.28,2976.05 60.11,2988.82 64.05,3001.3 69.05,3013.39 75.1,3025 82.13,3036.04 90.09,3046.42 98.93,3056.07 108.58,3064.91 118.96,3072.87 130,3079.9 141.61,3085.95 153.7,3090.95 166.18,3094.89 178.95,3097.72 191.93,3099.43 205,3100 218.07,3099.43 231.05,3097.72 243.82,3094.89 256.3,3090.95 268.39,3085.95 280,3079.9 291.04,3072.87 301.42,3064.91 311.07,3056.07 319.91,3046.42 327.87,3036.04 334.9,3025 340.95,3013.39 345.95,3001.3 349.89,2988.82 352.72,2976.05 354.43,2963.07 355,2950 354.43,2936.93 352.72,2923.95 349.89,2911.18 345.95,2898.7 340.95,2886.61 334.9,2875 327.87,2863.96 319.91,2853.58 311.07,2843.93 301.42,2835.09 291.04,2827.13 280,2820.1 268.39,2814.05 256.3,2809.05 243.82,2805.11 231.05,2802.28 218.07,2800.57 205,2800
Multi-Layer:
  region: 205,355 218.07,354.43 231.05,352.72 243.82,349.89 256.3,345.95 268.39,340.95 280,334.9 291.04,327.87 301.42,319.91 311.07,311.07 319.91,301.42 327.87,291.04 334.9,280 340.95,268.39 345.95,256.3 349.89,243.82 352.72,231.05 354.43,218.07 355,205 354.43,191.93 352.72,178.95 349.89,166.18 345.95,153.7 340.95,141.61 334.9,130 327.87,118.96 319.91,108.58 311.07,98.93 301.42,90.09 291.04,82.13 280,75.1 268.39,69.05 256.3,64.05 243.82,60.11 231.05,57.28 218.07,55.57 205,55 191.93,55.57 178.95,57.28 166.18,60.11 153.7,64.05 141.61,69.05 130,75.1 118.96,82.13 108.58,90.09 98.93,98.93 90.09,108.58 82.13,118.96 75.1,130 69.05,141.61 64.05,153.7 60.11,166.18 57.28,178.95 55.57,191.93 55,205 55.57,218.07 57.28,231.05 60.11,243.82 64.05,256.3 69.05,268.39 75.1,280 82.13,291.04 90.09,301.42 98.93,311.07 108.58,319.91 118.96,327.87 130,334.9 141.61,340.95 153.7,345.95 166.18,349.89 178.95,352.72 191.93,354.43 205,355
  region: 4813.23,3134.65 4811.58,3147.13 4806.77,3158.76 4799.1,3168.75 4789.11,3176.41 4777.48,3181.23 4765,3182.87 4752.52,3181.23 4740.89,3176.41 4730.9,3168.75 4723.23,3158.76 4718.42,3147.13 4716.77,3134.65 4718.42,3122.16 4723.23,3110.53 4730.9,3100.54 4740.89,3092.88 4752.52,3088.06 4765,3086.42 4777.48,3088.06 4789.11,3092.88 4799.1,3100.54 4806.77,3110.53 4811.58,3122.16 4813.23,3134.65
  region: 5120,355 5133.07,354.43 5146.05,352.72 5158.82,349.89 5171.3,345.95 5183.39,340.95 5195,334.9 5206.04,327.87 5216.42,319.91 5226.07,311.07 5234.91,301.42 5242.87,291.04 5249.9,280 5255.95,268.39 5260.95,256.3 5264.89,243.82 5267.72,231.05 5269.43,218.07 5270,205 5269.43,191.93 5267.72,178.95 5264.89,166.18 5260.95,153.7 5255.95,141.61 5249.9,130 5242.87,118.96 5234.91,108.58 5226.07,98.93 5216.42,90.09 5206.04,82.13 5195,75.1 5183.39,69.05 5171.3,64.05 5158.82,60.11 5146.05,57.28 5133.07,55.57 5120,55 5106.93,55.57 5093.95,57.28 5081.18,60.11 5068.7,64.05 5056.61,69.05 5045,75.1 5033.96,82.13 5023.58,90.09 5013.93,98.93 5005.09,108.58 4997.13,118.96 4990.1,130 4984.05,141.61 4979.05,153.7 4975.11,166.18 4972.28,178.95 4970.57,191.93 4970,205 4970.57,218.08 4972.28,231.05 4975.11,243.82 4979.05,256.3 4984.05,268.39 4990.1,280 4997.13,291.04 5005.09,301.42 5013.94,311.07 5023.58,319.91 5033.97,327.87 5045,334.9 5056.61,340.95 5068.7,345.95 5081.18,349.89 5093.95,352.72 5106.93,354.43 5120,355
  region: 5120,3100 5133.07,3099.43 5146.05,3097.72 5158.82,3094.89 5171.3,3090.95 5183.39,3085.95 5195,3079.9 5206.04,3072.87 5216.42,3064.91 5226.07,3056.07 5234.91,3046.42 5242.87,3036.04 5249.9,3025 5255.95,3013.39 5260.95,3001.3 5264.89,2988.82 5267.72,2976.05 5269.43,2963.07 5270,2950 5269.43,2936.93 5267.72,2923.95 5264.89,2911.18 5260.95,2898.7 5255.95,2886.61 5249.9,2875 5242.87,2863.96 5234.91,2853.58 5226.07,2843.93 5216.42,2835.09 5206.04,2827.13 5195,2820.1 5183.39,2814.05 5171.3,2809.05 5158.82,2805.11 5146.05,2802.28 5133.07,2800.57 5120,2800 5106.93,2800.57 5093.95,2802.28 5081.18,2805.11 5068.7,2809.05 5056.61,2814.05 5045,2820.1 5033.96,2827.13 5023.58,2835.09 5013.93,2843.93 5005.09,2853.58 4997.13,2863.96 4990.1,2875 4984.05,2886.61 4979.05,2898.7 4975.11,2911.18 4972.28,2923.95 4970.57,2936.93 4970,2950 4970.57,2963.07 4972.28,2976.05 4975.11,2988.82 4979.05,3001.3 4984.05,3013.39 4990.1,3025 4997.13,3036.04 5005.09,3046.42 5013.93,3056.07 5023.58,3064.91 5033.96,3072.87 5045,3079.9 5056.61,3085.95 5068.7,3090.95 5081.18,3094.89 5093.95,3097.72 5106.93,3099.43 5120,3100

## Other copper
TOP:
  drawing of 276 lines, arcs and shapes, not listed
L2-VCC:
  drawing of 167 lines, arcs and shapes, not listed
L3-GND:
  drawing of 153 lines, arcs and shapes, not listed
BOTTOM:
  drawing of 195 lines, arcs and shapes, not listed

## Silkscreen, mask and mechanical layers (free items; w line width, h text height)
OUTLINE:
  lines w1: 3.7,83.7 ccw(c83.7,83.7) 83.7,3.7 5238.66,3.7 ccw(c5238.66,83.7) 5318.66,83.7 5318.66,3467.01 ccw(c5238.66,3467.01) 5238.66,3547.01 83.7,3547.01 ccw(c83.7,3467.01) 3.7,3467.01 3.7,83.7
NCLEGEND-1-4:
  circle w1: c6722.5,1513 r19.68
  lines w1: 6273,-3612 11109,-3612 ; 6273,-3362 11109,-3362 ; 6273,-3112 11109,-3112 ; 6273,-2862 11109,-2862 ; 6273,-2612 11109,-2612 ; 6273,-2362 11109,-2362 ; 6273,-2112 11109,-2112 ; 6273,-1862 11109,-1862 ; 6273,-1612 11109,-1612 ; 6273,-1362 11109,-1362 ; 6273,-1112 11109,-1112 ; 6273,-862 11109,-862 ; 6273,-612 11109,-612 ; 6273,-362 11109,-362 ; 6273,-112 11109,-112 ; 6273,138 11109,138 ; 6273,388 11109,388 ; 6273,638 11109,638 ; 6273,888 11109,888 ; 6273,1138 11109,1138 ; 6273,1388 11109,1388 ; 6273,1638 11109,1638 ; 6273,1888 11109,1888 ; 6273,2138 11109,2138 ; 6273,2388 11109,2388 ; 6273,2638 11109,2638 ; 6273,2888 11109,2888 ; 6273,3138 11109,3138 ; 6273,3388 11109,3388 ; 6273,3638 11109,3638 ; 6273,3888 11109,3888 ; 6273,4138 11109,4138 ; 6273,4388 11109,4388 ; 6716.59,3763 6728.41,3763 ; 6722.5,3757.09 6722.5,3768.91 ; 7172,-3862 7172,4138 ; 9063,-3862 9063,4138 ; 10334,-3862 10334,4138 ; 6273,-3862 6273,4638 11109,4638 11109,-3862 6273,-3862 ; 6683.13,-3752.75 6683.13,-3721.25 6761.87,-3721.25 6761.87,-3752.75 6683.13,-3752.75 ; 6683.13,-3498.81 6683.13,-3475.19 6761.87,-3475.19 6761.87,-3498.81 6683.13,-3498.81 ; 6688.41,3013 6698.39,2988.89 6722.5,2978.91 6746.61,2988.89 6756.59,3013 6746.61,3037.11 6722.5,3047.09 6698.39,3037.11 6688.41,3013 ; 6693.25,1758.12 ccw(c6722.5,1758.12) 6751.75,1758.12 6751.75,1767.88 ccw(c6722.5,1767.88) 6693.25,1767.88 6693.25,1758.12 ; 6702.81,1248.24 6702.81,1277.76 6742.19,1277.76 6742.19,1248.24 6702.81,1248.24 ; 6705,2245.5 6722.5,2280.5 6740,2245.5 6705,2245.5 ; 6706.75,2505.13 6722.5,2497.25 6738.25,2505.13 6738.25,2520.87 6722.5,2528.75 6706.75,2520.87 6706.75,2505.13 ; 6706.75,2763 6722.5,2778.75 6738.25,2763 6722.5,2747.25 6706.75,2763 ; 6708.5,3263 6715.5,3249 6729.5,3249 6736.5,3263 6729.5,3277 6715.5,3277 6708.5,3263 ; 6716.59,3507.09 6728.41,3507.09 6728.41,3518.91 6716.59,3518.91 6716.59,3507.09 ; 6718,1986 ccw(c6718,2013) 6718,2040 6727,2040 ccw(c6727,2013) 6727,1986 6718,1986
  text "DRILL CHART: TOP to BOTTOM" at 7391,4450.5 h125
  text "ALL UNITS ARE IN MILS" at 7641,4200.5 h125
  text "FIGURE" at 6422.5,3950.5 h125
  text "SIZE" at 7917.5,3950.5 h125
  text "PLATED" at 9398.5,3950.5 h125
  text "QTY" at 10571.5,3950.5 h125
  text "11.811" at 7817.5,3700.5 h125
  text "PLATED" at 9398.5,3700.5 h125
  text "1964" at 10521.5,3700.5 h125
  text "11.811" at 7817.5,3450.5 h125
  text "PLATED" at 9398.5,3450.5 h125
  text "36" at 10621.5,3450.5 h125
  text "28.0" at 7917.5,3200.5 h125
  text "PLATED" at 9398.5,3200.5 h125
  text "18" at 10621.5,3200.5 h125
  text "31.496" at 7817.5,2950.5 h125
  text "PLATED" at 9398.5,2950.5 h125
  text "25" at 10621.5,2950.5 h125
  text "31.496" at 7817.5,2700.5 h125
  text "PLATED" at 9398.5,2700.5 h125
  text "30" at 10621.5,2700.5 h125
  text "31.496" at 7817.5,2450.5 h125
  text "PLATED" at 9398.5,2450.5 h125
  text "3" at 10671.5,2450.5 h125
  text "35.0" at 7917.5,2200.5 h125
  text "PLATED" at 9398.5,2200.5 h125
  text "20" at 10621.5,2200.5 h125
  text "36.0" at 7917.5,1950.5 h125
  text "PLATED" at 9398.5,1950.5 h125
  text "12" at 10621.5,1950.5 h125
  text "39.0" at 7917.5,1700.5 h125
  text "PLATED" at 9398.5,1700.5 h125
  text "2" at 10671.5,1700.5 h125
  text "39.37" at 7867.5,1450.5 h125
  text "PLATED" at 9398.5,1450.5 h125
  text "20" at 10621.5,1450.5 h125
  text "39.37" at 7867.5,1200.5 h125
  text "PLATED" at 9398.5,1200.5 h125
  text "2" at 10671.5,1200.5 h125
  text "40.0" at 7917.5,950.5 h125
  text "PLATED" at 9398.5,950.5 h125
  text "8" at 10671.5,950.5 h125
  text "40.0" at 7917.5,700.5 h125
  text "PLATED" at 9398.5,700.5 h125
  text "1" at 10671.5,700.5 h125
  text "65.0" at 7917.5,450.5 h125
  text "PLATED" at 9398.5,450.5 h125
  text "4" at 10671.5,450.5 h125
  text "66.929" at 7817.5,200.5 h125
  text "PLATED" at 9398.5,200.5 h125
  text "1" at 10671.5,200.5 h125
  text "66.929" at 7817.5,-49.5 h125
  text "PLATED" at 9398.5,-49.5 h125
  text "2" at 10671.5,-49.5 h125
  text "93.0" at 7917.5,-299.5 h125
  text "PLATED" at 9398.5,-299.5 h125
  text "4" at 10671.5,-299.5 h125
  text "102.362" at 7767.5,-549.5 h125
  text "PLATED" at 9398.5,-549.5 h125
  text "1" at 10671.5,-549.5 h125
  text "145.669" at 7767.5,-799.5 h125
  text "PLATED" at 9398.5,-799.5 h125
  text "4" at 10671.5,-799.5 h125
  text "23.622" at 7817.5,-1049.5 h125
  text "NON-PLATED" at 9198.5,-1049.5 h125
  text "4" at 10671.5,-1049.5 h125
  text "44.016" at 7817.5,-1299.5 h125
  text "NON-PLATED" at 9198.5,-1299.5 h125
  text "1" at 10671.5,-1299.5 h125
  text "45.0" at 7917.5,-1549.5 h125
  text "NON-PLATED" at 9198.5,-1549.5 h125
  text "1" at 10671.5,-1549.5 h125
  text "47.201" at 7817.5,-1799.5 h125
  text "NON-PLATED" at 9198.5,-1799.5 h125
  text "2" at 10671.5,-1799.5 h125
  text "55.0" at 7917.5,-2049.5 h125
  text "NON-PLATED" at 9198.5,-2049.5 h125
  text "1" at 10671.5,-2049.5 h125
  text "62.992" at 7817.5,-2299.5 h125
  text "NON-PLATED" at 9198.5,-2299.5 h125
  text "1" at 10671.5,-2299.5 h125
  text "65.0" at 7917.5,-2549.5 h125
  text "NON-PLATED" at 9198.5,-2549.5 h125
  text "1" at 10671.5,-2549.5 h125
  text "90.551" at 7817.5,-2799.5 h125
  text "NON-PLATED" at 9198.5,-2799.5 h125
  text "1" at 10671.5,-2799.5 h125
  text "127.949" at 7767.5,-3049.5 h125
  text "NON-PLATED" at 9198.5,-3049.5 h125
  text "2" at 10671.5,-3049.5 h125
  text "128.0" at 7867.5,-3299.5 h125
  text "NON-PLATED" at 9198.5,-3299.5 h125
  text "4" at 10671.5,-3299.5 h125
  text "78.74x23.622" at 7517.5,-3549.5 h125
  text "PLATED" at 9398.5,-3549.5 h125
  text "2" at 10671.5,-3549.5 h125
  text "78.74x31.5" at 7617.5,-3799.5 h125
  text "PLATED" at 9398.5,-3799.5 h125
  text "3" at 10671.5,-3799.5 h125
DRAWING_ORIGIN:
  lines w1: -25,0 25,0 ; 0,-25 0,25
Mechanical 255:
  drawing of 159 lines, arcs and shapes, not listed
